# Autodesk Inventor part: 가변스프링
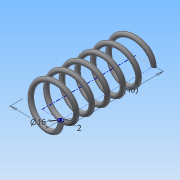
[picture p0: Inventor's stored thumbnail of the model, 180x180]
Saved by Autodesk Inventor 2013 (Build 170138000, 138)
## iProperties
Created: 2017-06
Part Number: 가변스프링
Material: 일반
Document SubType Name: Modeling
Designer: Administrator
Density: 1 g/cm^3
Author: Administrator
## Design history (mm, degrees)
sketch "스케치1"
  geometry: L1 (0, 0)-(8, 0); L2 (8, 0)-(8, 38); L3 (8, 38)-(0, 38); L4 (0, 38)-(0, 0); C1 r 1 at (8, 0)
  constraints: 8 end point, 2 parallel, 1 centre point, 1 coincident, 1 horizontal, 1 perpendicular
  dimensions: "d0" = 16 diameter of L2 L4; "d2" = 38 distance of L1.end L2.end (derived); "d3" = 2 diameter of C1
feature "코일1" sketch "스케치1" pitch "d4" = 10; turns "d6" = 6; dims "d5" = 38 (= d2), "d7" = 0, angle "d8" = 90 deg, angle "d9" = 90 deg, "d10" = 0, "d11" = 0
sketch "스케치2"
  geometry: L1 (39, 0)-(37, 0) reference; L2 (-1, 0)-(1, 0) reference; L3 (38, 24.641)-(0, 24.641); L4 (0, 24.641)-(0, -24.641); L5 (0, -24.641)-(38, -24.641); L6 (38, -24.641)-(38, 24.641); 5 further points
  constraints: 8 end point, 4 midpoint, 2 parallel, 1 horizontal, 1 horizontal alignment, 1 perpendicular
extrude "돌출1" sketch "스케치2" stored distance "d12" = 50; taper "d13" = 0 deg
node "솔리드1"
node "투영된 루프1"
